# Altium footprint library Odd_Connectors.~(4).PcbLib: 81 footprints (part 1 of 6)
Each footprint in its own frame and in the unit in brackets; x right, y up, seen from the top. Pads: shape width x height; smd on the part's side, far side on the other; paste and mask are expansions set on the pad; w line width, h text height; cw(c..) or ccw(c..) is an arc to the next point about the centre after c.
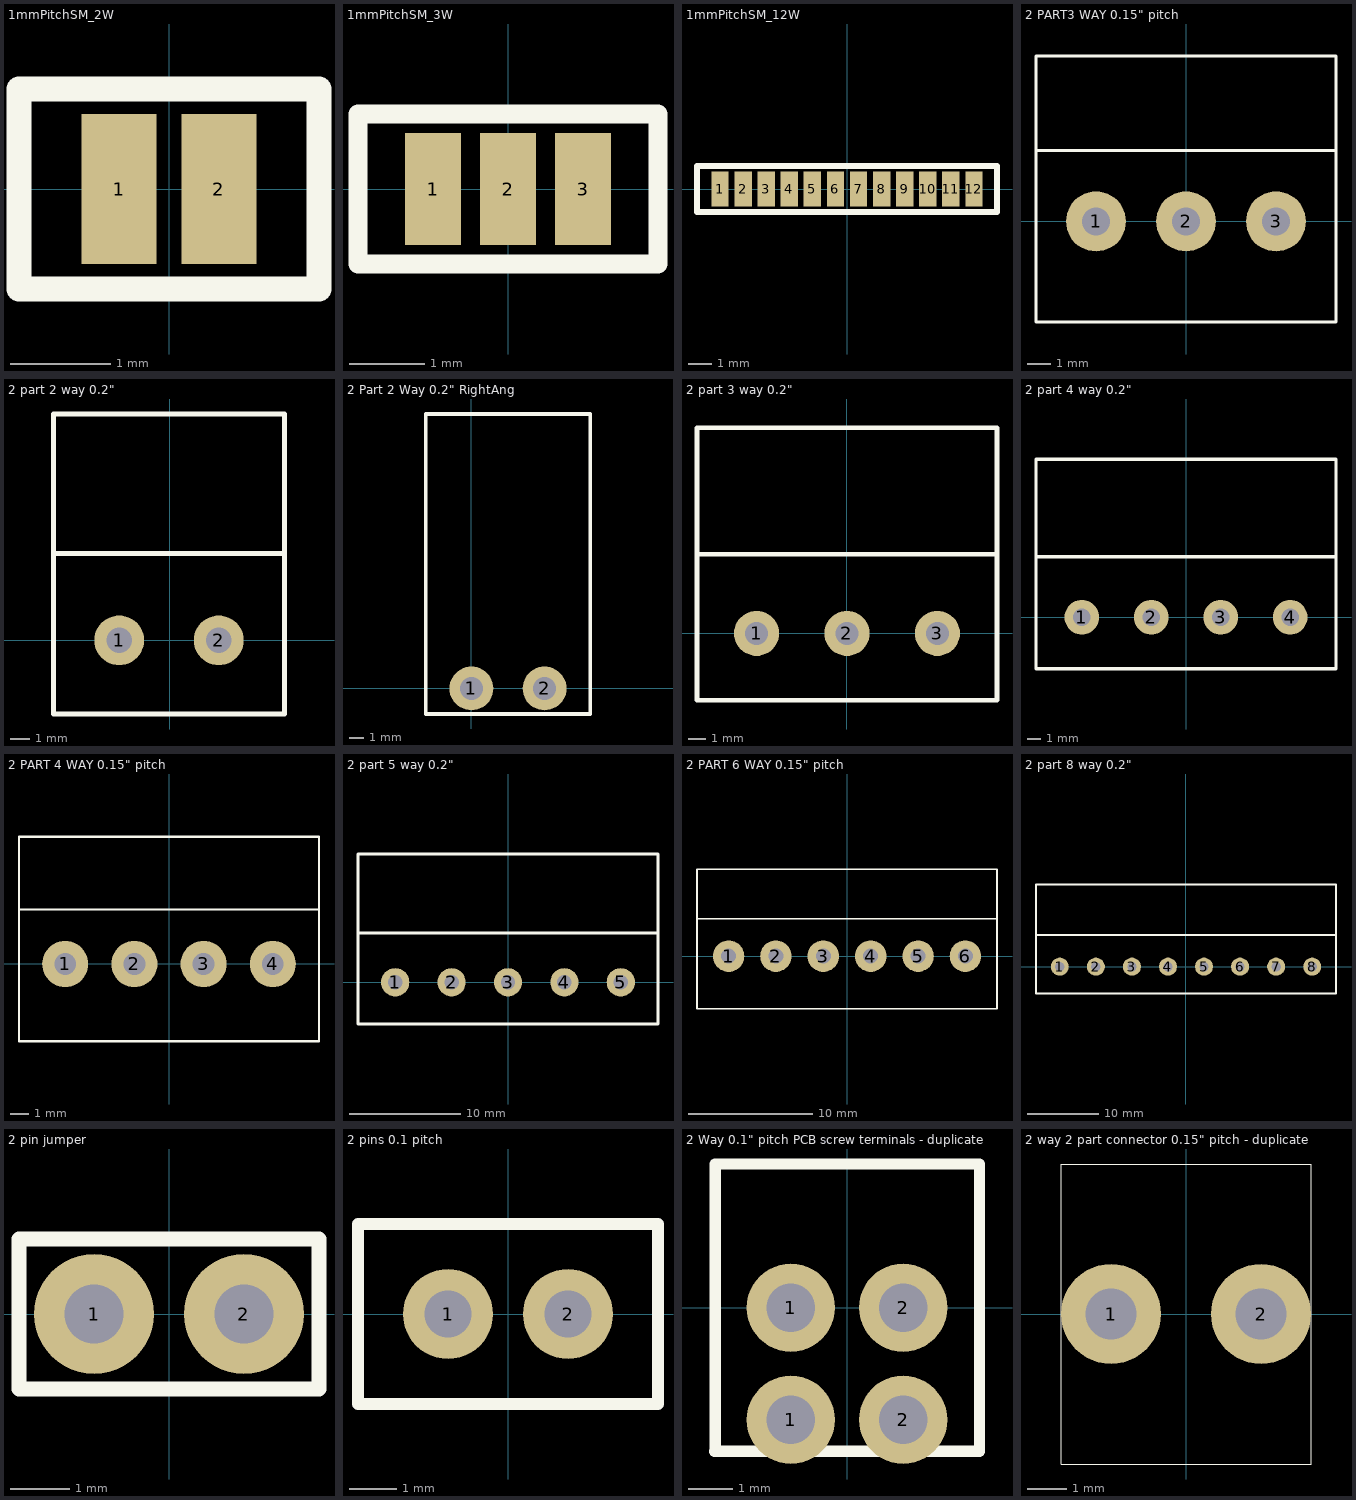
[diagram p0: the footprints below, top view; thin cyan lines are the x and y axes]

## 1mmPitchSM_2W [mm]
pads (2):
  rect 0.75x1.5 smd: 1(-0.5,0) 2(0.5,0)
Top Overlay:
  lines w0.254: -1.5,-1 -1.5,1 1.5,1 1.5,-1 -1.5,-1

## 1mmPitchSM_3W [mm]
pads (3):
  rect 0.75x1.5 smd: 1(-1,0) 2(0,0) 3(1,0)
Top Overlay:
  lines w0.254: -2,-1 -2,1 2,1 2,-1 -2,-1

## 1mmPitchSM_12W [mm]
pads (12):
  rect 0.75x1.5 smd: 1(-5.5,0) 2(-4.5,0) 3(-3.5,0) 4(-2.5,0) 5(-1.5,0) 6(-0.5,0) 7(0.5,0) 8(1.5,0) 9(2.5,0) 10(3.5,0) 11(4.5,0) 12(5.5,0)
Top Overlay:
  lines w0.254: -6.5,-1 6.5,-1 6.5,1 -6.5,1 -6.5,-1

## 2 PART3 WAY 0.15" pitch [mm]
height 20
pads (3):
  round 2.54 hole 1.2: 1(-3.81,0) 2(0,0) 3(3.81,0)
Top Overlay:
  lines w0.127: -6.35,3 6.35,3 ; -6.35,-4.25 6.35,-4.25 6.35,7 -6.35,7 -6.35,-4.25

## 2 part 2 way 0.2" [mm] "Two part connector (2 way) with plug shown"
height 12
pads (2):
  round 2.54 hole 1.3: 1(-2.58,0) 2(2.5,0)
Top Overlay:
  lines w0.254: -5.933,4.445 5.853,4.445 ; -5.933,-3.759 -5.933,11.557 5.853,11.557 5.853,-3.759 -5.933,-3.759

## 2 Part 2 Way 0.2" RightAng [mil] "2 part connector right angle 0.2\" pitch 2 way"
height 590.55
pads (2):
  round 120 hole 62.2: 1(0,0) 2(200,0)
Top Overlay:
  lines w10: -125,-70 -125,750 325,750 325,-70 -125,-70

## 2 part 3 way 0.2" [mm] "Two part connector (3 way) with plug shown"
height 12
pads (3):
  round 2.54 hole 1.3: 1(-5.08,0) 2(0,0) 3(5.08,0)
Top Overlay:
  lines w0.254: -8.433,4.445 8.433,4.445 ; -8.433,-3.759 8.433,-3.759 8.433,11.557 -8.433,11.557 -8.433,-3.759

## 2 part 4 way 0.2" [mm] "Two part connector (4 way) with plug shown"
height 12
pads (4):
  round 2.54 hole 1.3: 1(-7.62,0) 2(-2.54,0) 3(2.54,0) 4(7.62,0)
Top Overlay:
  lines w0.254: -10.973,4.445 10.973,4.445 ; -10.973,-3.759 10.973,-3.759 10.973,11.557 -10.973,11.557 -10.973,-3.759

## 2 PART 4 WAY 0.15" pitch [mm]
height 20
pads (4):
  round 2.54 hole 1.2: 1(-5.715,0) 2(-1.905,0) 3(1.905,0) 4(5.715,0)
Top Overlay:
  lines w0.127: -8.255,3 8.255,3 ; -8.255,-4.25 -8.255,7 8.255,7 8.255,-4.25 -8.255,-4.25

## 2 part 5 way 0.2" [mm] "Two part connector (4 way) with plug shown"
height 12
pads (5):
  round 2.54 hole 1.3: 1(-10.16,0) 2(-5.08,0) 3(0,0) 4(5.08,0) 5(10.16,0)
Top Overlay:
  lines w0.254: -13.513,4.445 13.513,4.445 ; -13.513,-3.759 13.513,-3.759 13.513,11.557 -13.513,11.557 -13.513,-3.759

## 2 PART 6 WAY 0.15" pitch [mm]
height 20
pads (6):
  round 2.54 hole 1.2: 1(-9.525,0) 2(-5.715,0) 3(-1.905,0) 4(1.905,0) 5(5.715,0) 6(9.525,0)
Top Overlay:
  lines w0.127: -12.065,3 12.065,3 ; -12.065,-4.25 -12.065,7 12.065,7 12.065,-4.25 -12.065,-4.25

## 2 part 8 way 0.2" [mm] "Two part connector (8 way) with plug shown"
height 12
pads (8):
  round 2.54 hole 1.3: 1(-17.78,0) 2(-12.7,0) 3(-7.62,0) 4(-2.54,0) 5(2.54,0) 6(7.62,0) 7(12.7,0) 8(17.78,0)
Top Overlay:
  lines w0.254: -21.133,4.445 21.133,4.445 ; -21.133,-3.759 -21.133,11.557 21.133,11.557 21.133,-3.759 -21.133,-3.759

## 2 pin jumper [mil] "2 pin jumper on 0.1\" pitch"
height 984.25
pads (2):
  round 80 hole 39.37: 1(-50,0) 2(50,0)
Top Overlay:
  lines w10: -100,-50 100,-50 100,50 -100,50 -100,-50

## 2 pins 0.1 pitch [mm] "pin header"
height 12
pads (2):
  round 1.905 hole 1: 1(-1.27,0) 2(1.27,0)
Top Overlay:
  lines w0.254: -3.175,-1.905 3.175,-1.905 3.175,1.905 -3.175,1.905 -3.175,-1.905

## 2 Way 0.1" pitch PCB screw terminals - duplicate [mm]
height 8.5
pads (4):
  round 2 hole 1.1: 1(-1.27,-2.54) 1(-1.27,0) 2(1.27,-2.54) 2(1.27,0)
Top Overlay:
  lines w0.254: -3,-3.25 3,-3.25 3,3.25 -2.98,3.25 -2.98,-3.25

## 2 way 2 part connector 0.15" pitch - duplicate [mm] "2 way connector or terminal block - 0.15\" pitch"
height 10.16
pads (2):
  round 2.54 hole 1.3 unplated: 1(-1.905,0) 2(1.905,0)
Top Overlay:
  lines w0.025: -3.175,-3.81 -3.175,3.81 3.175,3.81 3.175,-3.81 -3.175,-3.81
